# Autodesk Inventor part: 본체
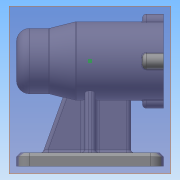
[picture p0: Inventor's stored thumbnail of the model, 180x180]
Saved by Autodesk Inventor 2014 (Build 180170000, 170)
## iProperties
Created: 2019-07
Part Number: 본체
Material: 일반
Document SubType Name: Modeling
Designer: net
Density: 1 g/cm^3
Appearance: 기본값
Author: net
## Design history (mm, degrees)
sketch "스케치1"
  geometry: L1 (-56, 0)-(56, 0); L2 (56, 30)-(-11, 30); L3 (-11, 30)-(-31, 25); L4 (-31, 25)-(-56, 25); L5 (56, 30)-(56, 21); L6 (56, 21)-(41, 21); L7 (41, 21)-(41, 24); L8 (41, 24)-(-13, 24); L9 (-13, 24)-(-13, 21); L10 (-13, 21)-(-25, 21); L11 (-25, 21)-(-25, 17.5); L12 (-25, 17.5)-(-43, 17.5); L13 (-43, 17.5)-(-43, 16); L14 (-43, 16)-(-47, 16); L15 (-47, 16)-(-47, 10.5); L16 (-47, 10.5)-(-50, 10.5); L17 (-50, 10.5)-(-50, 0); L18 (-56, 25)-(-56, 0); L19 (-50, 0)-(-56, 0); 2 further points
  constraints: 38 end point, 10 parallel, 6 perpendicular, 2 coincident, 2 vertical alignment, 1 collinear, 1 horizontal, 1 midpoint, 1 point on line
  dimensions: "d0" = 112 distance of L1.start L1.end; "d1" = 15 distance of L5.end L6.end; "d2" = 48 diameter of L8 L1; "d3" = 42 diameter of L10 L1; "d4" = 25 distance of L3.end L4.end; "d5" = 45 horizontal distance of L2.end L4.end; "d6" = 35 diameter of L12 L1; "d7" = 32 diameter of L14 L1; "d8" = 21 diameter of L16 L1; "d9" = 18 distance of L11.end L12.end; "d10" = 12 distance of L9.end L10.end; "d11" = 54 distance of L7.end L8.end; "d12" = 3 distance of L15.end L16.end; "d13" = 60 diameter of L2.end L1; "d14" = 50 diameter of L4.end L1; "d15" = 42 diameter of L5.end L1; "d69" = 4 distance of L13.end L14.end
revolve "회전1" sketch "스케치1" stored, may be unused: angle "d16" = 90 deg
sketch "스케치2"
  geometry: C1 r 6 at (-30, 0); C2 r 6 at (0, -30); C3 r 6 at (30, 0); C4 r 6 at (0, 30); A1 r 30 centre (0, 0) between (-30, 0) and (0, -30) reference
  constraints: 4 centre point, 4 point on circle
  dimensions: "d17" = 12 diameter of C1; "d18" = 12 diameter of C2; "d19" = 12 diameter of C3; "d20" = 12 diameter of C4
extrude "돌출1" join sketch "스케치2" distance "d21" = 16; taper "d22" = 0 deg
sketch "스케치3"
  geometry: A1 r 6 centre (0, 0) between (0.6, 5.97) and (0.6, -5.97) reference; A2 r 6 centre (30, -30) between (24.03, -29.4) and (35.97, -29.4) reference; A3 r 6 centre (60, 0) between (59.4, -5.97) and (59.4, 5.97) reference; A4 r 6 centre (30, 30) between (35.97, 29.4) and (24.03, 29.4) reference; 4 further points
  constraints: 4 coincident
hole "구멍1" sketch "스케치3" at (30, 30), (60, 0), (30, -30), (0, 0) diameter "d23" = 3.242; stored, may be unused: countersink angle "d27" = 90 deg, drill point angle "d29" = 118 deg; dims "d24" = 8, "d25" = 4, "d26" = 2, "d28" = 11
fillet "모깎기2" dims "d31" = 0.3
fillet "모깎기3" dims "d32" = 3
node "작업 평면1"
sketch "스케치4"
  geometry: L1 (-56, -35)-(56, -35); L2 (56, -35)-(56, 35); L3 (56, 35)-(-56, 35); L4 (-56, 35)-(-56, -35); L5 (-56, -35)-(56, 35); L6 (56, -35)-(-56, 35); 1 further point
  constraints: 12 end point, 2 midpoint, 2 parallel, 1 horizontal, 1 perpendicular
  dimensions: "d34" = 112 distance of L2.end L3.end; "d35" = 70 distance of L1.end L2.end
extrude "돌출2" join sketch "스케치4" distance "d36" = 10; taper "d37" = 0 deg
fillet "모깎기4" dims "d38" = 10
sketch "스케치5"
  geometry: C1 r 3 at (46, -25); C2 r 3 at (-46, -25); C3 r 3 at (-46, 25); C4 r 3 at (46, 25); A1 r 10 centre (-46, 25) between (-46, 35) and (-56, 25) reference; A2 r 10 centre (-46, -25) between (-56, -25) and (-46, -35) reference; A3 r 10 centre (46, -25) between (46, -35) and (56, -25) reference; A4 r 10 centre (46, 25) between (56, 25) and (46, 35) reference; 1 further point
  constraints: 4 centre point, 4 coincident
  dimensions: "d39" = 6 diameter of C1; "d40" = 6 diameter of C2; "d41" = 6 diameter of C3; "d42" = 6 diameter of C4
extrude "돌출3" cut sketch "스케치5" distance "d43" = 10; taper "d44" = 0 deg
sketch "스케치7"
  geometry: L1 (46, -70)-(-46, -70) reference; L2 (56, -80)-(56, -70) reference; L3 (-56, -70)-(-56, -80) reference; L4 (36, -70)-(19.742, -25.332); L5 (19.742, -25.332)-(-31, -25.332); L6 (-31, -25.332)-(-31, -70); L7 (36, -70)-(-31, -70); 3 further points
  constraints: 8 end point, 3 perpendicular, 2 point on line
  dimensions: "d49" = 20 distance from line of L2 L4.start; "d50" = 25 distance from line of L3 L6.end; "d51" = 110 deg angle of L1 L4
extrude "돌출4" join sketch "스케치7" stored distance "d52" = 8; taper "d53" = 0 deg
sketch "스케치8"
  geometry: L1 (35, -70)-(35, -80) reference; L2 (-35, -80)-(-35, -70) reference; L3 (-25, -70)-(25, -70) reference; L4 (25, -70)-(32, -70) reference; L5 (-32, -70)-(-25, -70) reference; L6 (28, -70)-(19.139, -19.747); L7 (-28, -70)-(-19.139, -19.747); L8 (28, -70)-(-28, -70); A1 r 27.5 centre (0, 0) between (-19.139, -19.747) and (19.139, -19.747); 3 further points
  constraints: 6 end point, 2 point on circle, 2 point on line, 1 centre point, 1 coincident, 1 collinear
  dimensions: "d56" = 7 horizontal distance of L1.end L6.start; "d57" = 7 horizontal distance of L2.start L7.start
extrude "돌출5" join sketch "스케치8" stored distance "d60" = 8; taper "d61" = 0 deg
fillet "모깎기6" dims "d62" = 3
fillet "모깎기7" dims "d63" = 3
chamfer "모따기1" distance "d64" = 3; stored, may be unused: second distance "d65" = 2, angle "d66" = 45 deg
fillet "모깎기8" dims "d67" = 10
fillet "모깎기9" dims "d68" = 3
fillet "모깎기10" dims "d70" = 1
fillet "모깎기11" dims "d71" = 3
chamfer "모따기2" distance "d72" = 1; stored, may be unused: second distance "d73" = 2, angle "d74" = 45 deg
node "작업 평면5"
sketch "스케치14"
  geometry: 1 further point
node "솔리드1"
other parameters: "d54" = 55, "d58" = 100 deg, "d59" = 100 deg
